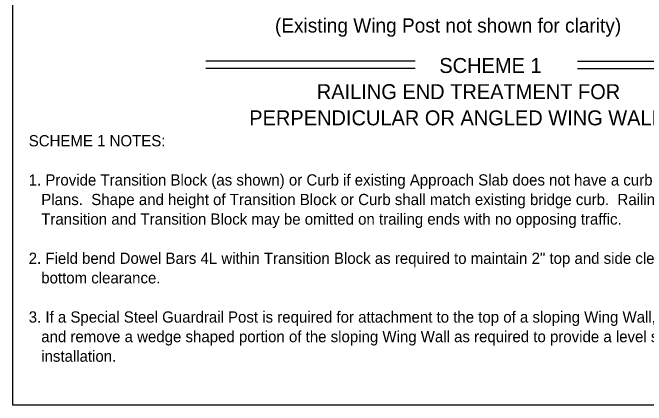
# Model space of a CAD drawing. Extents: x 1.5 to 68.7, y 0 to 31.
# Drawn here: x 1.47 to 12.85, y 1.78 to 8.84 of the extents above; entities that cross this region are included whole.
import ezdxf

# ---------------------------------------------------------------- set-up
doc = ezdxf.new("R2010")
doc.units = 0
doc.layers.add('ActivePts-ConstElements', color=7, linetype='Continuous')
doc.layers.add('Dimension', color=7, linetype='Continuous')

msp = doc.modelspace()

# ---------------------------------------------------------------- linework, layer by layer
at = {"layer": 'ActivePts-ConstElements'}
msp.add_lwpolyline([(1.467, 28.183), (42.533, 28.183), (42.533, 1.783), (1.467, 1.783)], close=True, dxfattribs=at)
at = {"layer": 'Dimension'}
for p, q in [((8.699, 7.968), (4.94, 7.968)), ((11.614, 7.968), (15.974, 7.968)), ((8.699, 7.835), (4.94, 7.835)), ((11.614, 7.835), (15.974, 7.835))]:
    msp.add_line(p, q, dxfattribs=at)

# ---------------------------------------------------------------- texts
for s, height, p in [('(Existing Wing Post not shown for clarity)', 0.256, (6.179, 8.484)), ('SCHEME 1', 0.2688, (9.132, 7.757)), ('RAILING END TREATMENT FOR ', 0.2688, (6.931, 7.287)), ('PERPENDICULAR OR ANGLED WING WALLS', 0.2688, (5.717, 6.816)), ('SCHEME 1 NOTES:', 0.2016, (1.755, 6.438)), ('1. Provide Transition Block (as shown) or Curb if existing Approach Slab does not have a curb, see Roadway ', 0.2016, (1.755, 5.734)), ('   Plans.  Shape and height of Transition Block or Curb shall match existing bridge curb.  Railing End ', 0.2016, (1.755, 5.382)), ('   Transition and Transition Block may be omitted on trailing ends with no opposing traffic.', 0.2016, (1.755, 5.03)), ('2. Field bend Dowel Bars 4L within Transition Block as required to maintain 2" top and side clearance and 3" ', 0.2016, (1.755, 4.326)), ('   bottom clearance.   ', 0.2016, (1.755, 3.974)), ('3. If a Special Steel Guardrail Post is required for attachment to the top of a sloping Wing Wall, saw cut ', 0.2016, (1.755, 3.27)), ('   and remove a wedge shaped portion of the sloping Wing Wall as required to provide a level surface for post', 0.2016, (1.755, 2.918)), ('   installation.', 0.2016, (1.755, 2.566))]:
    msp.add_text(s, height=height, dxfattribs=at).set_placement(p)

doc.saveas('drawing.dxf')
